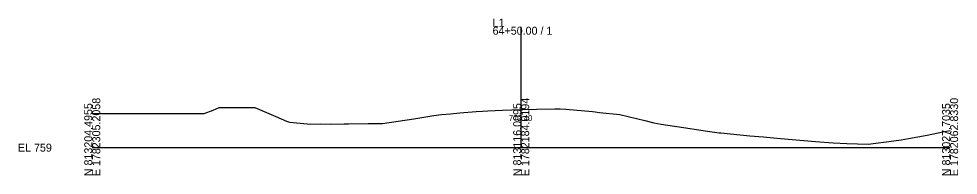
# Model space of a CAD drawing. Extents: x 5574 to 10203, y -10 to 9546.
# Drawn here: x 7574.3 to 7902.8, y 1990.3 to 2045.2 of the extents above; entities that cross this region are included whole.
import ezdxf

# ---------------------------------------------------------------- set-up
doc = ezdxf.new("R2010")
doc.units = 0
for name, color, linetype in [('Exist Cross Section Cell', 7, 'Continuous'), ('Exist XS Center Line Elevation Label', 7, 'Continuous'), ('Exist XS Ground Line', 7, 'Continuous')]:
    doc.layers.add(name, color=color, linetype=linetype)

msp = doc.modelspace()

# ---------------------------------------------------------------- linework, layer by layer
at = {"layer": 'Exist Cross Section Cell'}
for p, q in [((7750, 2000), (7750, 2042.42)), ((7600, 2000), (7750, 2000)), ((7750, 2000), (7900, 2000))]:
    msp.add_line(p, q, dxfattribs=at)
at = {"layer": 'Exist XS Ground Line'}
for p, q in [((7642.23, 2013.15), (7644.37, 2014.14)), ((7644.37, 2014.14), (7647.96, 2014.12)), ((7647.96, 2014.12), (7654.75, 2014.08)), ((7654.75, 2014.08), (7656.88, 2014.09)), ((7656.88, 2014.09), (7664.23, 2010.88)), ((7600, 2012.03), (7606.01, 2012.03)), ((7606.01, 2012.03), (7618.82, 2012.03)), ((7618.82, 2012.03), (7620.71, 2012.03)), ((7620.71, 2012.03), (7622.27, 2012.03)), ((7622.27, 2012.03), (7623.79, 2012.03)), ((7623.79, 2012.03), (7636.34, 2012.03)), ((7636.34, 2012.03), (7639.09, 2012.03)), ((7639.09, 2012.03), (7642.23, 2013.15)), ((7664.23, 2010.88), (7667.97, 2009.28)), ((7712.5, 2010.06), (7719.5, 2011.22)), ((7719.5, 2011.22), (7722.16, 2011.65)), ((7722.16, 2011.65), (7725.29, 2011.88)), ((7725.29, 2011.88), (7728.56, 2012.18)), ((7728.56, 2012.18), (7734.23, 2012.69)), ((7734.23, 2012.69), (7736.52, 2012.84)), ((7736.52, 2012.84), (7738.35, 2012.97)), ((7738.35, 2012.97), (7743.49, 2013.16)), ((7743.49, 2013.16), (7750, 2013.4)), ((7750, 2013.4), (7750.58, 2013.42)), ((7750.58, 2013.42), (7755.35, 2013.53)), ((7755.35, 2013.53), (7761.75, 2013.67)), ((7761.75, 2013.67), (7763.6, 2013.6)), ((7763.6, 2013.6), (7765.56, 2013.53)), ((7765.56, 2013.53), (7774.94, 2012.63)), ((7774.94, 2012.63), (7775.86, 2012.56)), ((7775.86, 2012.56), (7777.38, 2012.38)), ((7777.38, 2012.38), (7784.53, 2011.62)), ((7784.53, 2011.62), (7793.28, 2009.54)), ((7667.97, 2009.28), (7668.99, 2008.96)), ((7668.99, 2008.96), (7676.39, 2008.29)), ((7676.39, 2008.29), (7679.77, 2008.4)), ((7679.77, 2008.4), (7683.15, 2008.29)), ((7683.15, 2008.29), (7688.07, 2008.37)), ((7688.07, 2008.37), (7688.92, 2008.38)), ((7688.92, 2008.38), (7689.61, 2008.39)), ((7689.61, 2008.39), (7696.46, 2008.5)), ((7696.46, 2008.5), (7700.98, 2008.47)), ((7700.98, 2008.47), (7701.46, 2008.46)), ((7701.46, 2008.46), (7712.5, 2010.06)), ((7793.28, 2009.54), (7796.45, 2008.73)), ((7796.45, 2008.73), (7798.9, 2008.28)), ((7798.9, 2008.28), (7809.14, 2006.68)), ((7809.14, 2006.68), (7810.6, 2006.45)), ((7810.6, 2006.45), (7814.32, 2005.93)), ((7814.32, 2005.93), (7819.21, 2005.23)), ((7819.21, 2005.23), (7819.85, 2005.17)), ((7819.85, 2005.17), (7829.97, 2004.2)), ((7829.97, 2004.2), (7834.72, 2003.77)), ((7885.44, 2003.24), (7892.03, 2004.42)), ((7892.03, 2004.42), (7897.52, 2005.53)), ((7897.52, 2005.53), (7900, 2006.02)), ((7834.72, 2003.77), (7837.04, 2003.57)), ((7837.04, 2003.57), (7840.74, 2003.21)), ((7840.74, 2003.21), (7852.94, 2002.13)), ((7852.94, 2002.13), (7859.13, 2001.67)), ((7859.13, 2001.67), (7863.94, 2001.44)), ((7863.94, 2001.44), (7871.38, 2001.21)), ((7871.38, 2001.21), (7880.29, 2002.4)), ((7880.29, 2002.4), (7882.84, 2002.76)), ((7882.84, 2002.76), (7885.44, 2003.24))]:
    msp.add_line(p, q, dxfattribs=at)

# ---------------------------------------------------------------- texts
at = {"layer": 'Exist Cross Section Cell'}
for s, p in [('L1', (7740, 2042.42)), ('64+50.00 / 1', (7740, 2039.62)), ('EL 759', (7574, 1998.6))]:
    msp.add_text(s, height=2.8, dxfattribs=at).set_placement(p)
for s, p in [('E 1782305.2058', (7602.8, 1990)), ('E 1782184.0194', (7752.8, 1990)), ('E 1782062.8330', (7902.8, 1990)), ('N 813204.4955', (7600, 1990)), ('N 813116.0995', (7750, 1990)), ('N 813027.7035', (7900, 1990))]:
    msp.add_text(s, height=2.8, rotation=90, dxfattribs=at).set_placement(p)
at = {"layer": 'Exist XS Center Line Elevation Label'}
msp.add_text('772.40', height=2, dxfattribs=at).set_placement((7745.71, 2009.4))

doc.saveas('drawing.dxf')
